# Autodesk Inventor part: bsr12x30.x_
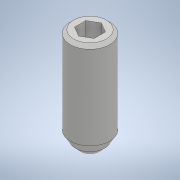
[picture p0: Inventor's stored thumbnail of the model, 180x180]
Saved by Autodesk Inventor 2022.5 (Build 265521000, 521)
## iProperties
Created: 2020-01
Part Number: bsr12x30.x_
Material: 一般
Document SubType Name: Modeling
Designer: ImaoCorp
Density: 1 g/cm^3
Appearance: 既定
Sending System: SOLIDWORKS 2018-2018316
MC: AMD64
MC_MODEL: Intel64 Family 6 Model 60 Stepping 3, GenuineIntel
OS: Windows_NT
FRU: Parasolid Version 30.0, build 310,  6- 8-2018
FORMAT: text
GUISE: transmit
KEY: bsr12x30
FILE: bsr12x30.x_t
DATE: Thu Jan 23 16:47:56 2020
Author: ImaoCorp
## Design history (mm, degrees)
feature "Base1"
node "ソリッド1"
